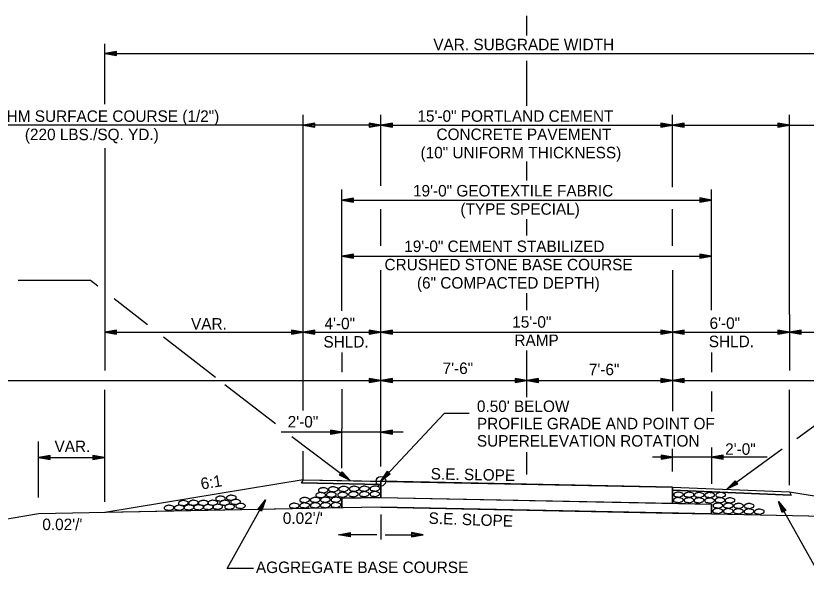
# Model space of a CAD drawing. Extents: x 1734743 to 1735935, y 759845 to 763831.
# Drawn here: x 1735731.28 to 1735771.91, y 759865.76 to 759894.43 of the extents above; entities that cross this region are included whole.
import ezdxf

# ---------------------------------------------------------------- set-up
doc = ezdxf.new("R2010")
doc.units = 0
for name, color, linetype in [('1', 7, 'Continuous'), ('19', 7, 'Continuous'), ('8', 7, 'Continuous'), ('Level 1', 7, 'Continuous'), ('Level 9', 7, 'Continuous'), ('R_Prop Surface', 7, 'Continuous')]:
    doc.layers.add(name, color=color, linetype=linetype)

# ---------------------------------------------------------------- blocks, each defined once
blk = doc.blocks.new('TM')
at = {"layer": '8'}
for p, q in [((-120.309, 21.181), (-119.787, -20.829)), ((0, 0), (-120.309, 21.181)), ((-31.382, 2.945), (-120.176, 10.512)), ((-119.787, -20.829), (0, 0)), ((-119.911, -10.826), (-31.307, -3.057))]:
    blk.add_line(p, q, dxfattribs=at)
blk = doc.blocks.new('ROCKS')
at = {"layer": '1'}
blk.add_spline([(0.013, 0.06), (0.053, 0.053), (0.107, 0.033), (0.133, 0.013), (0.133, -0.007), (0.12, -0.033), (0.107, -0.04), (0.073, -0.053), (0.033, -0.067), (0.013, -0.067), (-0.02, -0.06), (-0.06, -0.053), (-0.087, -0.047), (-0.113, -0.02), (-0.113, -0.007), (-0.107, 0.02), (-0.087, 0.033), (-0.067, 0.047), (-0.033, 0.053), (-0.02, 0.06), (0.013, 0.06)], degree=3, dxfattribs=at)

msp = doc.modelspace()

# ---------------------------------------------------------------- linework, layer by layer
at = {"layer": '19'}
for p, q in [((1735757.547, 759893.42), (1735757.548, 759894.428)), ((1735735.858, 759889.876), (1735735.858, 759892.979)), ((1735736.458, 759892.599), (1735735.858, 759892.494)), ((1735735.858, 759892.494), (1735779.32, 759892.494)), ((1735735.858, 759892.494), (1735736.458, 759892.389)), ((1735736.458, 759892.544), (1735736.018, 759892.509)), ((1735736.018, 759892.479), (1735736.458, 759892.439)), ((1735736.458, 759892.389), (1735736.458, 759892.599)), ((1735757.547, 759889.792), (1735757.548, 759892.106)), ((1735746.046, 759874.137), (1735746.046, 759889.344)), ((1735750.046, 759885.676), (1735750.046, 759889.344)), ((1735765.045, 759885.614), (1735765.046, 759889.344)), ((1735771.046, 759879.072), (1735771.046, 759889.344)), ((1735750.046, 759888.799), (1735727.238, 759888.799)), ((1735746.646, 759888.904), (1735746.046, 759888.799)), ((1735746.046, 759888.799), (1735746.646, 759888.694)), ((1735746.646, 759888.849), (1735746.206, 759888.814)), ((1735746.206, 759888.784), (1735746.646, 759888.744)), ((1735746.646, 759888.694), (1735746.646, 759888.904)), ((1735749.446, 759888.904), (1735749.446, 759888.694)), ((1735750.046, 759888.799), (1735749.446, 759888.904)), ((1735749.886, 759888.814), (1735749.446, 759888.849)), ((1735749.446, 759888.694), (1735750.046, 759888.799)), ((1735749.446, 759888.744), (1735749.886, 759888.784)), ((1735750.646, 759888.904), (1735750.046, 759888.799)), ((1735750.046, 759888.799), (1735765.046, 759888.799)), ((1735750.046, 759888.799), (1735750.646, 759888.694)), ((1735750.646, 759888.849), (1735750.206, 759888.814)), ((1735750.206, 759888.784), (1735750.646, 759888.744)), ((1735750.646, 759888.694), (1735750.646, 759888.904)), ((1735764.446, 759888.904), (1735764.446, 759888.694)), ((1735765.046, 759888.799), (1735764.446, 759888.904)), ((1735764.886, 759888.814), (1735764.446, 759888.849)), ((1735764.446, 759888.694), (1735765.046, 759888.799)), ((1735764.446, 759888.744), (1735764.886, 759888.784)), ((1735765.646, 759888.904), (1735765.046, 759888.799)), ((1735765.046, 759888.799), (1735788.756, 759888.799)), ((1735765.046, 759888.799), (1735765.646, 759888.694)), ((1735765.646, 759888.849), (1735765.206, 759888.814)), ((1735765.206, 759888.784), (1735765.646, 759888.744)), ((1735765.646, 759888.694), (1735765.646, 759888.904)), ((1735770.446, 759888.904), (1735770.446, 759888.694)), ((1735771.046, 759888.799), (1735770.446, 759888.904)), ((1735770.886, 759888.814), (1735770.446, 759888.849)), ((1735770.446, 759888.694), (1735771.046, 759888.799)), ((1735770.446, 759888.744), (1735770.886, 759888.784)), ((1735735.858, 759887.623), (1735735.858, 759876.188)), ((1735757.546, 759885.96), (1735757.546, 759886.93)), ((1735748.046, 759879.264), (1735748.046, 759885.499)), ((1735767.045, 759879.287), (1735767.045, 759885.499)), ((1735748.646, 759885.058), (1735748.046, 759884.954)), ((1735748.046, 759884.954), (1735767.045, 759884.954)), ((1735748.046, 759884.954), (1735748.646, 759884.848)), ((1735748.646, 759885.003), (1735748.206, 759884.969)), ((1735748.206, 759884.939), (1735748.646, 759884.898)), ((1735748.646, 759884.848), (1735748.646, 759885.058)), ((1735766.446, 759885.059), (1735766.446, 759884.849)), ((1735767.046, 759884.954), (1735766.446, 759885.059)), ((1735766.886, 759884.969), (1735766.446, 759885.004)), ((1735766.446, 759884.849), (1735767.046, 759884.954)), ((1735766.446, 759884.899), (1735766.886, 759884.939)), ((1735750.046, 759882.591), (1735750.046, 759884.483)), ((1735765.045, 759882.591), (1735765.045, 759884.483)), ((1735757.546, 759883.126), (1735757.546, 759883.977)), ((1735748.646, 759882.169), (1735748.046, 759882.064)), ((1735748.046, 759882.064), (1735767.045, 759882.064)), ((1735748.046, 759882.064), (1735748.646, 759881.959)), ((1735748.646, 759882.114), (1735748.206, 759882.079)), ((1735748.206, 759882.049), (1735748.646, 759882.009)), ((1735748.646, 759881.959), (1735748.646, 759882.169)), ((1735766.445, 759882.169), (1735766.445, 759881.959)), ((1735767.045, 759882.064), (1735766.445, 759882.169)), ((1735766.885, 759882.079), (1735766.445, 759882.114)), ((1735766.445, 759881.959), (1735767.045, 759882.064)), ((1735766.445, 759882.009), (1735766.885, 759882.049)), ((1735750.046, 759871.244), (1735750.046, 759881.351)), ((1735765.046, 759881.355), (1735765.046, 759876.583)), ((1735731.401, 759880.831), (1735735.119, 759880.831)), ((1735735.119, 759880.831), (1735735.491, 759880.542)), ((1735736.338, 759879.886), (1735738.046, 759878.56)), ((1735757.546, 759879.297), (1735757.546, 759880.166)), ((1735746.047, 759876.187), (1735746.047, 759879.072)), ((1735771.046, 759879.072), (1735771.046, 759876.187)), ((1735736.458, 759878.27), (1735735.858, 759878.165)), ((1735736.458, 759878.215), (1735736.018, 759878.18)), ((1735736.458, 759878.06), (1735736.458, 759878.27)), ((1735745.446, 759878.27), (1735745.446, 759878.06)), ((1735746.046, 759878.165), (1735745.446, 759878.27)), ((1735745.886, 759878.18), (1735745.446, 759878.215)), ((1735746.646, 759878.27), (1735746.046, 759878.165)), ((1735746.646, 759878.215), (1735746.206, 759878.18)), ((1735746.646, 759878.06), (1735746.646, 759878.27)), ((1735749.446, 759878.27), (1735749.446, 759878.06)), ((1735750.046, 759878.165), (1735749.446, 759878.27)), ((1735749.886, 759878.18), (1735749.446, 759878.215)), ((1735750.646, 759878.27), (1735750.046, 759878.165)), ((1735750.646, 759878.215), (1735750.206, 759878.18)), ((1735750.646, 759878.06), (1735750.646, 759878.27)), ((1735764.446, 759878.27), (1735764.446, 759878.06)), ((1735765.046, 759878.165), (1735764.446, 759878.27)), ((1735764.886, 759878.18), (1735764.446, 759878.215)), ((1735765.646, 759878.27), (1735765.046, 759878.165)), ((1735765.646, 759878.215), (1735765.206, 759878.18)), ((1735765.646, 759878.06), (1735765.646, 759878.27)), ((1735770.446, 759878.27), (1735770.446, 759878.06)), ((1735771.046, 759878.165), (1735770.446, 759878.27)), ((1735770.886, 759878.18), (1735770.446, 759878.215)), ((1735771.646, 759878.27), (1735771.046, 759878.165)), ((1735771.646, 759878.215), (1735771.206, 759878.18)), ((1735771.646, 759878.06), (1735771.646, 759878.27)), ((1735735.858, 759878.165), (1735736.458, 759878.06)), ((1735735.858, 759878.165), (1735746.046, 759878.165)), ((1735736.018, 759878.15), (1735736.458, 759878.11)), ((1735738.871, 759877.92), (1735741.551, 759875.841)), ((1735745.446, 759878.06), (1735746.046, 759878.165)), ((1735745.446, 759878.11), (1735745.886, 759878.15)), ((1735746.046, 759878.165), (1735746.646, 759878.06)), ((1735746.046, 759878.165), (1735750.046, 759878.165)), ((1735746.206, 759878.15), (1735746.646, 759878.11)), ((1735749.446, 759878.06), (1735750.046, 759878.165)), ((1735749.446, 759878.11), (1735749.886, 759878.15)), ((1735750.046, 759878.165), (1735750.646, 759878.06)), ((1735750.046, 759878.165), (1735765.046, 759878.165)), ((1735750.206, 759878.15), (1735750.646, 759878.11)), ((1735764.446, 759878.06), (1735765.046, 759878.165)), ((1735764.446, 759878.11), (1735764.886, 759878.15)), ((1735765.046, 759878.165), (1735765.646, 759878.06)), ((1735765.046, 759878.165), (1735771.046, 759878.165)), ((1735765.206, 759878.15), (1735765.646, 759878.11)), ((1735770.446, 759878.06), (1735771.046, 759878.165)), ((1735770.446, 759878.11), (1735770.886, 759878.15)), ((1735771.046, 759878.165), (1735771.646, 759878.06)), ((1735771.046, 759878.165), (1735779.32, 759878.165)), ((1735771.206, 759878.15), (1735771.646, 759878.11)), ((1735748.046, 759877.112), (1735748.046, 759876.106)), ((1735757.546, 759874.813), (1735757.547, 759877.213)), ((1735767.045, 759877.112), (1735767.045, 759876.106)), ((1735765.046, 759876.583), (1735765.046, 759874.098)), ((1735749.446, 759875.78), (1735749.446, 759875.57)), ((1735750.046, 759875.675), (1735749.446, 759875.78)), ((1735750.646, 759875.78), (1735750.046, 759875.675)), ((1735750.646, 759875.57), (1735750.646, 759875.78)), ((1735756.946, 759875.78), (1735756.946, 759875.57)), ((1735757.546, 759875.675), (1735756.946, 759875.78)), ((1735758.146, 759875.78), (1735757.546, 759875.675)), ((1735758.146, 759875.57), (1735758.146, 759875.78)), ((1735764.446, 759875.78), (1735764.446, 759875.57)), ((1735765.046, 759875.675), (1735764.446, 759875.78)), ((1735765.646, 759875.78), (1735765.046, 759875.675)), ((1735765.646, 759875.57), (1735765.646, 759875.78)), ((1735720.047, 759875.677), (1735750.046, 759875.675)), ((1735742.03, 759875.47), (1735744.623, 759873.459)), ((1735749.886, 759875.69), (1735749.446, 759875.725)), ((1735749.446, 759875.57), (1735750.046, 759875.675)), ((1735749.446, 759875.62), (1735749.886, 759875.66)), ((1735750.046, 759875.675), (1735750.646, 759875.57)), ((1735750.046, 759875.675), (1735757.546, 759875.675)), ((1735750.646, 759875.725), (1735750.206, 759875.69)), ((1735750.206, 759875.66), (1735750.646, 759875.62)), ((1735757.386, 759875.69), (1735756.946, 759875.725)), ((1735756.946, 759875.57), (1735757.546, 759875.675)), ((1735756.946, 759875.62), (1735757.386, 759875.66)), ((1735757.546, 759875.675), (1735765.046, 759875.675)), ((1735757.546, 759875.675), (1735758.146, 759875.57)), ((1735758.146, 759875.725), (1735757.706, 759875.69)), ((1735757.706, 759875.66), (1735758.146, 759875.62)), ((1735764.886, 759875.69), (1735764.446, 759875.725)), ((1735764.446, 759875.57), (1735765.046, 759875.675)), ((1735764.446, 759875.62), (1735764.886, 759875.66)), ((1735765.046, 759875.675), (1735765.646, 759875.57)), ((1735765.046, 759875.675), (1735795.046, 759875.675)), ((1735765.646, 759875.725), (1735765.206, 759875.69)), ((1735765.206, 759875.66), (1735765.646, 759875.62)), ((1735735.857, 759869.427), (1735735.858, 759875.202)), ((1735748.046, 759871.164), (1735748.047, 759875.231)), ((1735767.045, 759875.107), (1735767.045, 759874.08)), ((1735771.046, 759870.288), (1735771.046, 759875.201)), ((1735771.434, 759872.696), (1735775.048, 759875.318)), ((1735753.294, 759873.974), (1735750.046, 759870.494)), ((1735754.584, 759873.974), (1735753.294, 759873.974)), ((1735751.197, 759873.02), (1735744.922, 759873.02)), ((1735747.448, 759873.125), (1735747.448, 759872.915)), ((1735748.048, 759873.02), (1735747.448, 759873.125)), ((1735747.888, 759873.035), (1735747.448, 759873.07)), ((1735747.448, 759872.915), (1735748.048, 759873.02)), ((1735747.448, 759872.965), (1735747.888, 759873.005)), ((1735750.647, 759873.125), (1735750.047, 759873.02)), ((1735750.047, 759873.02), (1735750.647, 759872.915)), ((1735750.647, 759873.07), (1735750.207, 759873.035)), ((1735750.207, 759873.005), (1735750.647, 759872.965)), ((1735750.647, 759872.915), (1735750.647, 759873.125)), ((1735732.447, 759869.654), (1735732.447, 759872.531)), ((1735745.472, 759872.799), (1735748.463, 759870.525)), ((1735765.046, 759870.992), (1735765.046, 759872.153)), ((1735767.045, 759872.225), (1735767.045, 759870.352)), ((1735767.83, 759870.081), (1735770.684, 759872.152)), ((1735733.039, 759871.824), (1735732.439, 759871.719)), ((1735732.439, 759871.719), (1735733.039, 759871.614)), ((1735732.447, 759871.718), (1735735.858, 759871.718)), ((1735733.039, 759871.769), (1735732.599, 759871.734)), ((1735733.039, 759871.614), (1735733.039, 759871.824)), ((1735735.242, 759871.817), (1735735.242, 759871.607)), ((1735735.682, 759871.727), (1735735.242, 759871.762)), ((1735735.242, 759871.607), (1735735.842, 759871.712)), ((1735735.842, 759871.712), (1735735.242, 759871.817)), ((1735746.046, 759870.574), (1735746.046, 759872.043)), ((1735757.546, 759870.843), (1735757.547, 759871.987)), ((1735769.897, 759871.73), (1735764.017, 759871.73)), ((1735764.447, 759871.835), (1735764.447, 759871.625)), ((1735765.047, 759871.73), (1735764.447, 759871.835)), ((1735764.887, 759871.745), (1735764.447, 759871.78)), ((1735764.447, 759871.625), (1735765.047, 759871.73)), ((1735764.447, 759871.675), (1735764.887, 759871.715)), ((1735767.645, 759871.835), (1735767.045, 759871.73)), ((1735767.045, 759871.73), (1735767.645, 759871.625)), ((1735767.645, 759871.78), (1735767.205, 759871.745)), ((1735767.205, 759871.715), (1735767.645, 759871.675)), ((1735767.645, 759871.625), (1735767.645, 759871.835)), ((1735732.599, 759871.704), (1735733.039, 759871.664)), ((1735735.242, 759871.657), (1735735.682, 759871.697)), ((1735747.921, 759870.803), (1735748.047, 759870.969)), ((1735748.022, 759870.931), (1735748.343, 759870.634)), ((1735748.047, 759870.969), (1735748.463, 759870.525)), ((1735750.046, 759870.494), (1735750.379, 759871.004)), ((1735750.146, 759870.617), (1735750.415, 759870.963)), ((1735750.379, 759871.004), (1735750.531, 759870.86)), ((1735746.047, 759870.574), (1735735.858, 759868.878)), ((1735746.046, 759870.574), (1735765.046, 759870.192)), ((1735748.463, 759870.525), (1735747.921, 759870.803)), ((1735748.33, 759870.613), (1735747.957, 759870.843)), ((1735750.531, 759870.86), (1735750.046, 759870.494)), ((1735750.046, 759869.66), (1735750.046, 759870.494)), ((1735750.495, 759870.889), (1735750.167, 759870.601)), ((1735767.83, 759870.081), (1735768.252, 759870.52)), ((1735768.252, 759870.52), (1735768.375, 759870.351)), ((1735745.963, 759870.409), (1735750.046, 759870.327)), ((1735765.046, 759870.192), (1735771.046, 759869.952)), ((1735765.046, 759870.192), (1735765.046, 759869.359)), ((1735768.375, 759870.351), (1735767.83, 759870.081)), ((1735767.951, 759870.183), (1735768.279, 759870.474)), ((1735768.345, 759870.386), (1735767.968, 759870.164)), ((1735765.046, 759870.026), (1735771.131, 759869.782)), ((1735771.046, 759869.952), (1735779.32, 759868.572)), ((1735742.14, 759866.012), (1735744.115, 759869.535)), ((1735743.731, 759869.063), (1735744.115, 759869.535)), ((1735743.773, 759869.044), (1735744.023, 759869.402)), ((1735744.046, 759869.392), (1735743.868, 759868.991)), ((1735744.115, 759869.535), (1735743.913, 759868.961)), ((1735750.046, 759869.66), (1735748.046, 759869.621)), ((1735748.046, 759869.621), (1735748.046, 759869.12)), ((1735750.046, 759869.66), (1735765.046, 759869.359)), ((1735765.046, 759869.359), (1735767.046, 759869.319)), ((1735767.046, 759868.819), (1735767.046, 759869.319)), ((1735770.683, 759868.882), (1735770.479, 759869.455)), ((1735770.479, 759869.455), (1735770.865, 759868.984)), ((1735772.392, 759866.063), (1735770.479, 759869.455)), ((1735770.721, 759868.907), (1735770.545, 759869.308)), ((1735770.566, 759869.322), (1735770.816, 759868.962)), ((1735748.109, 759869.122), (1735732.447, 759868.81)), ((1735748.046, 759869.12), (1735735.858, 759868.878)), ((1735743.913, 759868.961), (1735743.731, 759869.063)), ((1735750.046, 759869.16), (1735748.046, 759869.12)), ((1735750.047, 759869.16), (1735748.109, 759869.122)), ((1735750.046, 759869.16), (1735765.046, 759868.859)), ((1735750.047, 759869.16), (1735767.057, 759868.819)), ((1735770.865, 759868.984), (1735770.683, 759868.882)), ((1735732.447, 759868.81), (1735720.048, 759866.747)), ((1735750.046, 759868.791), (1735750.046, 759867.504)), ((1735765.046, 759868.859), (1735767.046, 759868.819)), ((1735767.046, 759868.819), (1735779.32, 759868.572)), ((1735767.056, 759868.819), (1735782.729, 759868.504)), ((1735749.83, 759867.742), (1735747.875, 759867.742)), ((1735750.263, 759867.742), (1735752.217, 759867.742)), ((1735743.489, 759866.012), (1735742.14, 759866.012))]:
    msp.add_line(p, q, dxfattribs=at)
for points in [[(1735750.046, 759870.327), (1735745.963, 759870.409), (1735745.963, 759870.409), (1735746.046, 759870.574), (1735746.046, 759870.574), (1735746.046, 759870.574), (1735750.046, 759870.494), (1735750.046, 759870.494), (1735750.046, 759870.494), (1735750.046, 759870.327), (1735750.046, 759870.327), (1735750.046, 759870.327)], [(1735771.131, 759869.782), (1735765.046, 759870.026), (1735765.046, 759870.026), (1735765.046, 759870.192), (1735765.046, 759870.192), (1735765.046, 759870.192), (1735771.046, 759869.952), (1735771.046, 759869.952), (1735771.046, 759869.952), (1735771.131, 759869.782), (1735771.131, 759869.782), (1735771.131, 759869.782)], [(1735748.046, 759869.12), (1735748.046, 759869.621), (1735750.046, 759869.66), (1735767.046, 759869.319), (1735767.046, 759868.819), (1735767.046, 759868.819), (1735767.046, 759868.819), (1735750.046, 759869.16), (1735748.046, 759869.12)]]:
    msp.add_lwpolyline(points, dxfattribs=at)
msp.add_lwpolyline([(1735765.046, 759870.192), (1735750.046, 759870.494), (1735750.046, 759869.66), (1735765.046, 759869.359)], close=True, dxfattribs=at)
at = {"layer": 'Level 9'}
msp.add_circle((1735750.046, 759870.494), 0.25, dxfattribs=at)
at = {"layer": 'R_Prop Surface'}
for p, q in [((1735746.046, 759870.574), (1735745.963, 759870.409)), ((1735771.046, 759869.952), (1735771.131, 759869.782))]:
    msp.add_line(p, q, dxfattribs=at)

# ---------------------------------------------------------------- block references
at = {"layer": '19', "xscale": 0.0050063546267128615}
for p, yscale, rotation in [((1735747.873, 759867.739), -0.00500635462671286, -179.20057588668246), ((1735752.218, 759867.739), 0.00500635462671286, -0.7994241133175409)]:
    msp.add_blockref('TM', p, dxfattribs=dict(at, yscale=yscale, rotation=rotation))
at = {"layer": 'Level 1'}
for p, xscale, yscale, rotation in [((1735747.062, 759870.039), 2.0116542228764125, 2.0116542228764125, 0.9122903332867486), ((1735747.577, 759870.087), 2.0116542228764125, 2.0116542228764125, 0.9122903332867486), ((1735748.109, 759870.104), 2.011654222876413, 2.0116542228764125, 2.4691189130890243), ((1735748.652, 759870.11), 2.011654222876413, 2.0116542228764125, 2.4691189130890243), ((1735749.174, 759870.116), 2.011654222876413, 2.0116542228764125, 2.4691189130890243), ((1735749.716, 759870.122), 2.011654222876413, 2.0116542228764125, 2.4691189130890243), ((1735741.781, 759869.606), 2.011654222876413, 2.011654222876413, 1.8263814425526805), ((1735742.339, 759869.65), 2.011654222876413, 2.011654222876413, 1.8263814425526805), ((1735746.108, 759869.537), 2.011654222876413, 2.0116542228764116, 2.4173363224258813), ((1735746.651, 759869.542), 2.011654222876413, 2.0116542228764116, 2.4173363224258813), ((1735746.935, 759869.787), 2.0116542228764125, 2.0116542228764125, 0.9122903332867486), ((1735747.173, 759869.548), 2.011654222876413, 2.0116542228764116, 2.4173363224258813), ((1735747.481, 759869.811), 2.0116542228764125, 2.0116542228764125, 0.9122903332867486), ((1735747.716, 759869.553), 2.011654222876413, 2.0116542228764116, 2.4173363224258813), ((1735748.056, 759869.804), 2.011654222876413, 2.0116542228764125, 2.4691189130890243), ((1735748.616, 759869.83), 2.011654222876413, 2.0116542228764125, 2.4691189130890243), ((1735749.172, 759869.836), 2.011654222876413, 2.0116542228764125, 2.4691189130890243), ((1735749.714, 759869.842), 2.011654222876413, 2.0116542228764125, 2.4691189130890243), ((1735765.325, 759869.813), 2.0116542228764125, 2.0116542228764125, 0.9122903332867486), ((1735765.868, 759869.805), 2.0116542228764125, 2.0116542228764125, 0.9122903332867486), ((1735766.39, 759869.796), 2.0116542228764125, 2.0116542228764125, 0.9122903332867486), ((1735766.932, 759869.788), 2.0116542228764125, 2.0116542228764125, 0.9122903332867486), ((1735767.498, 759869.796), 2.0116542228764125, 2.0116542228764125, 0.9122903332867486), ((1735739.138, 759869.133), 2.011654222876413, 2.011654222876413, 1.8263814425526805), ((1735739.66, 759869.139), 2.011654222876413, 2.011654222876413, 1.8263814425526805), ((1735739.87, 759869.378), 2.011654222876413, 2.011654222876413, 1.8263814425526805), ((1735740.159, 759869.153), 2.011654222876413, 2.011654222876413, 1.8263814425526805), ((1735740.391, 759869.393), 2.011654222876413, 2.011654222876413, 1.8263814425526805), ((1735740.655, 759869.163), 2.011654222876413, 2.011654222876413, 1.8263814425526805), ((1735740.898, 759869.386), 2.011654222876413, 2.011654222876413, 1.8263814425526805), ((1735741.152, 759869.171), 2.011654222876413, 2.011654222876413, 1.8263814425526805), ((1735741.39, 759869.392), 2.011654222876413, 2.011654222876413, 1.8263814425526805), ((1735741.642, 759869.187), 2.011654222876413, 2.011654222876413, 1.8263814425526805), ((1735741.998, 759869.392), 2.011654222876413, 2.011654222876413, 1.8263814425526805), ((1735742.25, 759869.187), 2.011654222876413, 2.011654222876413, 1.8263814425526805), ((1735742.556, 759869.436), 2.011654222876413, 2.011654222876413, 1.8263814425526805), ((1735742.808, 759869.231), 2.011654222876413, 2.011654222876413, 1.8263814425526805), ((1735745.577, 759869.239), 2.0116542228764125, 2.0116542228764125, 0.9122903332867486), ((1735746.106, 759869.257), 2.011654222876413, 2.0116542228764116, 2.4173363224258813), ((1735746.649, 759869.262), 2.011654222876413, 2.0116542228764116, 2.4173363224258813), ((1735747.171, 759869.268), 2.011654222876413, 2.0116542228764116, 2.4173363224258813), ((1735747.713, 759869.273), 2.011654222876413, 2.0116542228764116, 2.4173363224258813), ((1735765.315, 759869.533), 2.0116542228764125, 2.0116542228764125, 0.9122903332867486), ((1735765.859, 759869.525), 2.0116542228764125, 2.0116542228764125, 0.9122903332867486), ((1735766.38, 759869.517), 2.0116542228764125, 2.0116542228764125, 0.9122903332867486), ((1735766.923, 759869.508), 2.0116542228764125, 2.0116542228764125, 0.9122903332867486), ((1735767.351, 759869.251), 2.0116542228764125, 2.0116542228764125, 0.9122903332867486), ((1735767.456, 759869.527), 2.0116542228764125, 2.0116542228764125, 0.9122903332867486), ((1735767.894, 759869.243), 2.0116542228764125, 2.0116542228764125, 0.9122903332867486), ((1735767.977, 759869.517), 2.0116542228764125, 2.0116542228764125, 0.9122903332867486), ((1735768.416, 759869.234), 2.0116542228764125, 2.0116542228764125, 0.9122903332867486), ((1735768.958, 759869.226), 2.0116542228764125, 2.0116542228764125, 0.9122903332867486), ((1735767.341, 759868.972), 2.0116542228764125, 2.0116542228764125, 0.9122903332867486), ((1735767.884, 759868.963), 2.0116542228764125, 2.0116542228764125, 0.9122903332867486), ((1735768.406, 759868.955), 2.0116542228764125, 2.0116542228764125, 0.9122903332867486), ((1735768.948, 759868.946), 2.0116542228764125, 2.0116542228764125, 0.9122903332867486), ((1735769.483, 759868.934), 2.0116542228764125, 2.0116542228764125, 0.9122903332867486)]:
    msp.add_blockref('ROCKS', p, dxfattribs=dict(at, xscale=xscale, yscale=yscale, rotation=rotation))

# ---------------------------------------------------------------- texts
at = {"layer": '19'}
for s, height, rotation, p in [('VAR. SUBGRADE WIDTH', 0.59001, 359.9954, (1735752.742, 759892.658)), ('4\'-0" ACHM SURFACE COURSE (1/2")', 0.59001, 359.9954, (1735727.919, 759888.975)), ('15\'-0" PORTLAND CEMENT', 0.59001, 359.9954, (1735751.925, 759888.979)), ('(220 LBS./SQ. YD.)', 0.59001, 359.9954, (1735731.742, 759888.034)), ('CONCRETE PAVEMENT', 0.59001, 359.9954, (1735752.905, 759888.039)), ('(10" UNIFORM THICKNESS)', 0.59001, 359.9954, (1735752.085, 759887.099)), ('19\'-0" GEOTEXTILE FABRIC', 0.59001, 359.9954, (1735751.698, 759885.138)), ('(TYPE SPECIAL)', 0.59001, 359.9954, (1735754.135, 759884.198)), ('19\'-0" CEMENT STABILIZED ', 0.59001, 359.9954, (1735751.247, 759882.28)), ('CRUSHED STONE BASE COURSE', 0.59001, 359.9954, (1735750.232, 759881.34)), ('(6" COMPACTED DEPTH)', 0.59001, 359.9954, (1735751.9, 759880.4)), ('VAR.', 0.59, 359.9954, (1735740.286, 759878.293)), ('4\'-0"', 0.59, 359.9954, (1735747.147, 759878.31)), ('15\'-0"', 0.59, 359.9954, (1735756.8, 759878.389)), ('6\'-0"', 0.59, 359.9954, (1735766.943, 759878.328)), ('SHLD.', 0.59, 359.9954, (1735747.094, 759877.37)), ('RAMP', 0.59, 359.9954, (1735756.911, 759877.449)), ('SHLD.', 0.59, 359.9954, (1735766.904, 759877.388)), ('7\'-6"', 0.59, 359.9954, (1735753.219, 759876.007)), ('7\'-6"', 0.59, 359.9954, (1735760.737, 759875.945)), ("0.50' BELOW ", 0.59001, 359.9954, (1735754.983, 759874.055)), ('2\'-0"', 0.59, 359.9954, (1735745.255, 759873.258)), ('PROFILE GRADE AND POINT OF ', 0.59001, 359.9954, (1735754.983, 759873.165)), ('VAR.', 0.59, 359.9954, (1735733.268, 759871.991)), ('SUPERELEVATION ROTATION', 0.59001, 359.9954, (1735754.983, 759872.275)), ('2\'-0"', 0.59, 359.9954, (1735767.745, 759871.854)), ('S.E. SLOPE', 0.59, 358.8496, (1735752.602, 759870.587)), ('6:1', 0.59, 9.4465, (1735740.831, 759870.064)), ("0.02'/'", 0.59, 359.9954, (1735745.005, 759868.301)), ('S.E. SLOPE', 0.59, 357.8898, (1735752.489, 759868.309)), ("0.02'/'", 0.59, 359.9954, (1735732.641, 759867.98)), ('AGGREGATE BASE COURSE', 0.59001, 360, (1735743.621, 759865.773))]:
    msp.add_text(s, height=height, rotation=rotation, dxfattribs=at).set_placement(p)

doc.saveas('drawing.dxf')
